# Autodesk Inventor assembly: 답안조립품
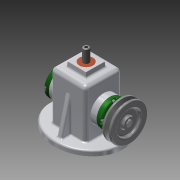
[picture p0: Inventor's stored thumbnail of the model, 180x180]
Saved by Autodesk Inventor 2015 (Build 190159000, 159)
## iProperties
Created: 2017-07
Part Number: 답안조립품
Document SubType Name: Assembly
Designer: Administrator
Author: Administrator
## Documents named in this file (15)
- C:\Users\Administrator\Desktop\답안조립품.iam
- C:\Users\Administrator\Desktop\본체.ipt
- C:\Users\Administrator\Desktop\470707V1030\V벨트풀리.ipt
- C:\Users\Administrator\Desktop\470707V1030\고정핀 1.2 x  8.ipt
- C:\Users\Administrator\Desktop\470707V1030\뒤커버.ipt
- C:\Users\Administrator\Desktop\470707V1030\링크.ipt
- C:\Users\Administrator\Desktop\470707V1030\베어링 12 x 32 x 10.ipt
- C:\Users\Administrator\Desktop\470707V1030\볼트 M4 x 12.ipt
- C:\Users\Administrator\Desktop\470707V1030\부시.ipt
- C:\Users\Administrator\Desktop\470707V1030\슬라이드.ipt
- C:\Users\Administrator\Desktop\470707V1030\앞커버.ipt
- C:\Users\Administrator\Desktop\470707V1030\오일실 12 25 7.ipt
- C:\Users\Administrator\Desktop\470707V1030\키 4 x 4 x 10.ipt
- C:\Users\Administrator\Desktop\470707V1030\편심축.ipt
- C:\Users\Administrator\Desktop\470707V1030\핀 5 x 18.ipt
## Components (3 placed, 3 different names)
1. V벨트풀리:1
2. 고정핀 1.2 x  8:1
3. 핀 5 x 18:1
